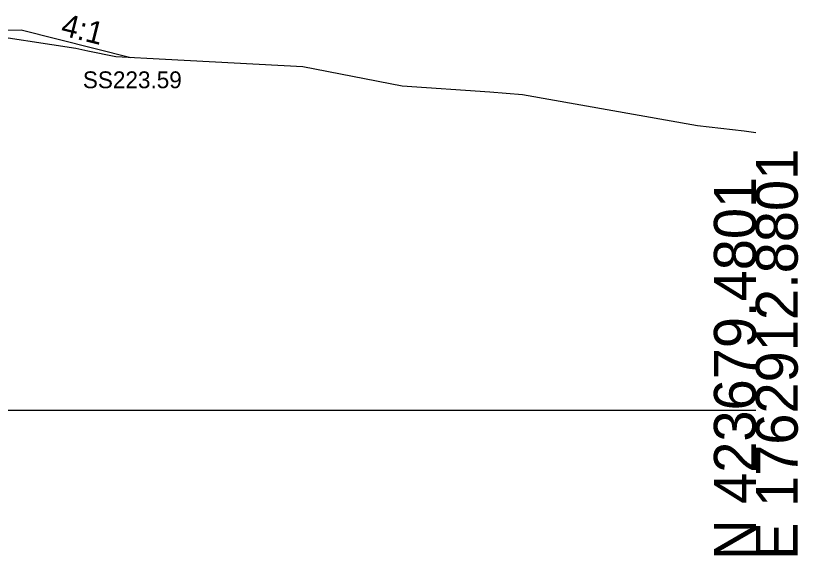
# Model space of a CAD drawing. Extents: x -26 to 3203, y -11010 to 4024.
# Drawn here: x 1150.6 to 1202.8, y -1009.7 to -973.6 of the extents above; entities that cross this region are included whole.
import ezdxf

# ---------------------------------------------------------------- set-up
doc = ezdxf.new("R2010")
doc.units = 0
for name, color, linetype in [('Exist Cross Section Cell', 7, 'Continuous'), ('Exist XS Ground Line', 7, 'Continuous'), ('Prop CMT Slope Grass', 7, 'Continuous'), ('Prop XS Side Slope Text', 7, 'Continuous'), ('Prop XS SS Elevation Text', 7, 'Continuous'), ('Scratch_Level_0', 7, 'Continuous')]:
    doc.layers.add(name, color=color, linetype=linetype)

msp = doc.modelspace()

# ---------------------------------------------------------------- linework, layer by layer
at = {"layer": 'Exist Cross Section Cell'}
msp.add_line((1100, -1000), (1200, -1000), dxfattribs=at)
at = {"layer": 'Exist XS Ground Line'}
msp.add_lwpolyline([(1147.848, -974.768), (1154.579, -975.787), (1155.384, -975.975), (1157.25, -976.362), (1160.575, -976.52), (1169.741, -977.011), (1176.379, -978.318), (1182.239, -978.706), (1184.422, -978.903), (1196.095, -980.959), (1199.23, -981.322), (1200, -981.422)], dxfattribs=at)
msp.add_lwpolyline([(1147.848, -974.768), (1154.579, -975.787), (1155.384, -975.975), (1157.25, -976.362), (1160.575, -976.52), (1169.741, -977.011), (1176.379, -978.318), (1182.239, -978.706), (1184.422, -978.903), (1196.095, -980.959), (1199.23, -981.322), (1200, -981.422)], dxfattribs=at)
msp.add_lwpolyline([(1147.848, -974.768), (1154.579, -975.787), (1155.384, -975.975), (1157.25, -976.362), (1160.575, -976.52), (1169.741, -977.011), (1176.379, -978.318), (1182.239, -978.706), (1184.422, -978.903), (1196.095, -980.959), (1199.23, -981.322), (1200, -981.422)], dxfattribs=at)
msp.add_lwpolyline([(1147.848, -974.768), (1154.579, -975.787), (1155.384, -975.975), (1157.25, -976.362), (1160.575, -976.52), (1169.741, -977.011), (1176.379, -978.318), (1182.239, -978.706), (1184.422, -978.903), (1196.095, -980.959), (1199.23, -981.322), (1200, -981.422)], dxfattribs=at)
msp.add_lwpolyline([(1147.848, -974.768), (1154.579, -975.787), (1155.384, -975.975), (1157.25, -976.362), (1160.575, -976.52), (1169.741, -977.011), (1176.379, -978.318), (1182.239, -978.706), (1184.422, -978.903), (1196.095, -980.959), (1199.23, -981.322), (1200, -981.422)], dxfattribs=at)
at = {"layer": 'Prop CMT Slope Grass'}
msp.add_lwpolyline([(1147.414, -974.645), (1150.914, -974.575), (1158.252, -976.41)], dxfattribs=at)

# ---------------------------------------------------------------- texts
at = {"layer": 'Exist Cross Section Cell'}
for s, p in [('E 1762912.8801', (1202.8, -1010)), ('N 423679.4801', (1200, -1010))]:
    msp.add_text(s, height=2.8, rotation=90, dxfattribs=at).set_placement(p)
at = {"layer": 'Prop XS Side Slope Text'}
msp.add_text('4:1', height=1.5, rotation=345.9638, dxfattribs=at).set_placement((1153.502, -974.913))
at = {"layer": 'Prop XS SS Elevation Text'}
msp.add_text('SS223.59', height=1.125, dxfattribs=at).set_placement((1155.044, -978.472))
at = {"layer": 'Scratch_Level_0'}
for s, p in [('RT_CSLP_Pnt', (1150.816, -974.585)), ('Exterior Boundary', (1158.093, -976.42)), ('RT_Slope_Fill', (1158.157, -976.42))]:
    msp.add_text(s, height=0.02, dxfattribs=at).set_placement(p)

doc.saveas('drawing.dxf')
